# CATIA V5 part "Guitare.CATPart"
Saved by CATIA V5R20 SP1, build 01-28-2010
Part number: Guitare
Bounding box of the stored display mesh (mm): x -301.947 to 418.384, y -248.286 to 329.798, z 0 to 50
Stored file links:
  F:\Pro\Emplois\1_Chercheur\ThinkMOTION\MMS\MMS_GR1\abruchon\Catia\Guitare.CATPart
  F:\Pro\Emplois\1_Chercheur\ThinkMOTION\MMS\MMS_GR1\abruchon\Catia\Vibrato.CATProduct
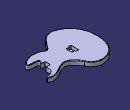
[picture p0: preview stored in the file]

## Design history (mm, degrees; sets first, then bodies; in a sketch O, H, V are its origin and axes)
External parameters (linked from other documents)
  External.largeur_chevalet = 60 mm
  External.Largeur_vibrato = 90 mm
  External.Longueur_bati = 30 mm
  External.Hauteur_vibrato = 40 mm
  External.decalage_axe = 5 mm
Set1
  Plane1: linked copy from another document
  Plane2: linked copy from another document
Body1 (main body)
  Sketch1 on xy-plane, origin (0, 0, 0), H (1, 0, 0), V (0, 1, 0)
    spline S1 through (33.3838, 244.1925) (206.3838, 146.2952) (349.3838, 210.2952) (418.3838, 196.2952)
    spline S2 through (33.3838, 244.1925) (-64, 327) (-215, 284) (-295, 133) (-290, -42) (-151, -219) (45, -201) (137, -90) (366, -100) (412, -52) (296, -24) (320, 19)
    spline S3 through (418.3838, 196.2952) (409, 178)
    spline S4 through (409, 178) (327, 146.2952) (320, 79)
    line L1 (320, 79) -> (269, 79)
    point P1 (320, 79)
    line L2 (320, 19) -> (269, 19)
    point P3 (320, 19)
    line L3 (269, 19) -> (269, 79)
    point P5 (33.3838, 244.1925)
    point P6 (33.3838, 244.1925)
    point P7 (418.3838, 196.2952)
    point P8 (418.3838, 196.2952)
    point P9 (409, 178)
    point P10 (409, 178)
    point P11 (320, 79)
    point P12 (320, 19)
    distance L2 L1 = 60 {= External.largeur_chevalet}
    coincidence: P6 P5, P7 P8, P9 P10, P11 P1, P12 P3
    horizontal: L1 H, L2 H
    vertical: L3 V
  Pad1: profile Sketch1, direction (0, 0, 1), length 50
  Sketch2 on end face of Pad1, origin (0, 0, 50), H (1, 0, 0), V (0, 1, 0)
    line L1 (18, 19) -> (18, 79)
    line L2 (18, 79) -> (-12, 79)
    reference projected line E1 (269, 79) -> (320, 79) from edge [face of Pad1 from Sketch1.L1 | end face of Pad1]
    line L3 (18, 19) -> (-12, 19)
    line L4 (-12, 79) -> (-12, 94)
    line L5 (-12, 19) -> (-12, 4)
    line L6 (-12, 94) -> (-47, 94)
    line L7 (-12, 4) -> (-47, 4)
    point P8 (-47, 4)
    line L8 (-47, 94) -> (-47, 4)
    point P9 (-47, 4)
    length L1 = 60 {= External.largeur_chevalet}
    distance L2 E1 = 0
    length L2 = 30 {= External.Longueur_bati}
    length L3 = 30 {= External.Longueur_bati}
    length L5 = 15 {= External.Largeur_vibrato /2-External.largeur_chevalet /2}
    length L4 = 15 {= External.Largeur_vibrato /2-External.largeur_chevalet /2}
    length L7 = 35 {= External.decalage_axe +External.Longueur_bati}
    length L6 = 35 {= External.decalage_axe +External.Longueur_bati}
    vertical: L1 V, L4 V, L5 V
    horizontal: L2 H, L3 H, L6 H, L7 H
    coincidence: L8 P8, P8 P9
  Pocket1: profile Sketch2, direction (0, 0, -1), length 40 {= External.Hauteur_vibrato}
  Fillet1: radius 5, on edge [face of Pad1 from Sketch1.S2 | face of Pad1 from Sketch1.S1]
  Fillet2: radius 5, on edge [face of Pad1 from Sketch1.S2 | end face of Pad1]
  Sketch3 on end face of Pad1, origin (0, 0, 50), H (1, 0, 0), V (0, 1, 0)
    circle A1 centre (10.921, 86) radius 3
    point P1 (10.921, 86)
    reference projected line E1 (18, 19) -> (18, 79) from edge [end face of Pad1 | face of Pocket1 from Sketch2.L1]
    reference intersected line E2 through (0, 79) direction (1, 0) from Plane1
    circle A2 centre (10.921, 12) radius 3
    reference intersected line E3 through (0, 19) direction (1, 0) from Plane2
    reference projected line E4 (18, 19) -> (18, 79) from edge [end face of Pad1 | face of Pocket1 from Sketch2.L1]
    radius A1 = 3
    distance P1 E1 = 7.079
    radius A1 = 3 (reference)
    distance E2 A1 = 4
    distance A2 E3 = 4
    radius A2 = 3
    distance A2 E4 = 4.079
  Pocket2: profile Sketch3, direction (0, 0, -1), length 10
  Pocket3: profile Sketch3, direction (0, 0, -1), length 10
